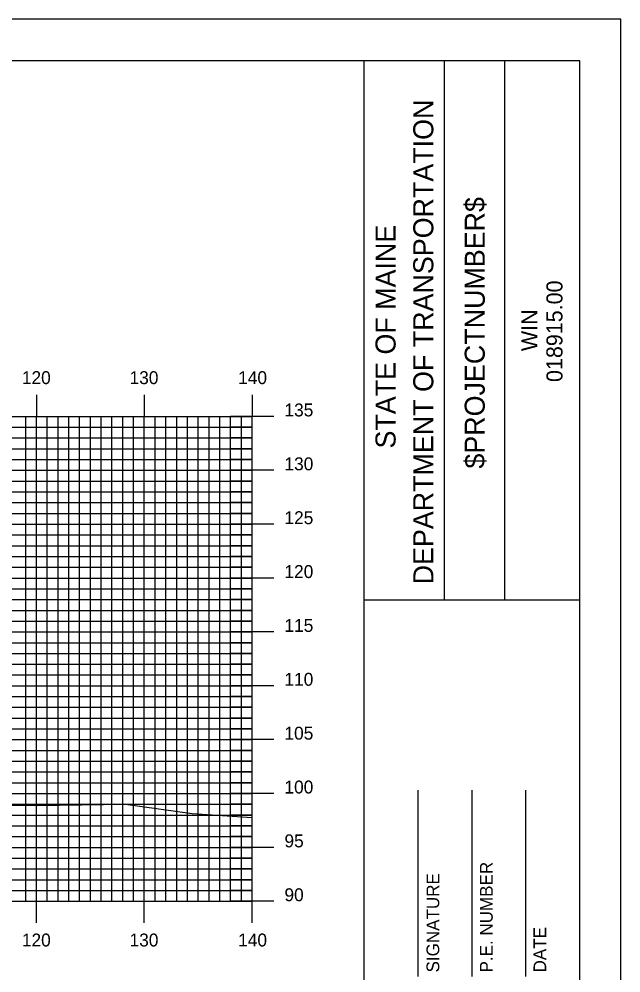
# Model space of a CAD drawing. Extents: x 1785402 to 1785745, y 442591 to 442811.
# Drawn here: x 1785685.9 to 1785741.8, y 442722 to 442810.5 of the extents above; entities that cross this region are included whole.
import ezdxf

# ---------------------------------------------------------------- set-up
doc = ezdxf.new("R2010")
doc.units = 0
for name, color, linetype in [('BORDER', 7, 'Continuous'), ('H_V ANNOTATION', 7, 'Continuous'), ('MAJOR', 7, 'Continuous'), ('MINOR', 7, 'Continuous'), ('PLOT BOUNDARY', 7, 'Continuous'), ('S_Roadway_Centerline', 7, 'Continuous')]:
    doc.layers.add(name, color=color, linetype=linetype)

msp = doc.modelspace()

# ---------------------------------------------------------------- linework, layer by layer
at = {"layer": 'BORDER'}
for p, q in [((1785717.939, 442596.665), (1785717.939, 442806.665)), ((1785725.396, 442756.659), (1785725.396, 442806.659)), ((1785730.986, 442756.659), (1785730.986, 442806.659)), ((1785717.941, 442756.653), (1785737.939, 442756.653)), ((1785717.941, 442756.653), (1785737.939, 442756.653)), ((1785722.939, 442721.671), (1785722.939, 442738.966)), ((1785722.939, 442721.671), (1785722.939, 442738.966)), ((1785727.939, 442721.671), (1785727.939, 442738.966)), ((1785727.939, 442721.671), (1785727.939, 442738.966)), ((1785732.939, 442721.671), (1785732.939, 442738.966)), ((1785732.939, 442721.671), (1785732.939, 442738.966))]:
    msp.add_line(p, q, dxfattribs=at)
msp.add_lwpolyline([(1785417.939, 442596.665), (1785737.939, 442596.665), (1785737.939, 442806.665), (1785417.939, 442806.665)], close=True, dxfattribs=at)
at = {"layer": 'MAJOR'}
for p, q in [((1785687.539, 442775.669), (1785687.539, 442773.665)), ((1785697.539, 442775.669), (1785697.539, 442773.665)), ((1785707.539, 442775.669), (1785707.539, 442773.665)), ((1785427.539, 442773.665), (1785707.539, 442773.665)), ((1785427.539, 442773.665), (1785707.539, 442773.665)), ((1785687.539, 442728.665), (1785687.539, 442773.665)), ((1785697.539, 442728.665), (1785697.539, 442773.665)), ((1785709.543, 442773.665), (1785705.535, 442773.665)), ((1785707.539, 442728.665), (1785707.539, 442773.665)), ((1785707.539, 442728.665), (1785707.539, 442773.665)), ((1785427.539, 442768.665), (1785707.539, 442768.665)), ((1785709.543, 442768.665), (1785705.535, 442768.665)), ((1785427.539, 442763.665), (1785707.539, 442763.665)), ((1785709.543, 442763.665), (1785705.535, 442763.665)), ((1785427.539, 442758.665), (1785707.539, 442758.665)), ((1785709.543, 442758.665), (1785705.535, 442758.665)), ((1785427.539, 442753.665), (1785707.539, 442753.665)), ((1785709.543, 442753.665), (1785705.535, 442753.665)), ((1785427.539, 442748.665), (1785707.539, 442748.665)), ((1785709.543, 442748.665), (1785705.535, 442748.665)), ((1785427.539, 442743.665), (1785707.539, 442743.665)), ((1785709.543, 442743.665), (1785705.535, 442743.665)), ((1785427.539, 442738.665), (1785707.539, 442738.665)), ((1785709.543, 442738.665), (1785705.535, 442738.665)), ((1785427.539, 442733.665), (1785707.539, 442733.665)), ((1785709.543, 442733.665), (1785705.535, 442733.665)), ((1785427.539, 442728.665), (1785707.539, 442728.665)), ((1785427.539, 442728.665), (1785707.539, 442728.665)), ((1785687.539, 442726.661), (1785687.539, 442728.665)), ((1785697.539, 442726.661), (1785697.539, 442728.665)), ((1785709.543, 442728.665), (1785705.535, 442728.665)), ((1785707.539, 442726.661), (1785707.539, 442728.665))]:
    msp.add_line(p, q, dxfattribs=at)
at = {"layer": 'MINOR'}
for p, q in [((1785686.539, 442728.665), (1785686.539, 442773.665)), ((1785688.539, 442728.665), (1785688.539, 442773.665)), ((1785689.539, 442728.665), (1785689.539, 442773.665)), ((1785690.539, 442728.665), (1785690.539, 442773.665)), ((1785691.539, 442728.665), (1785691.539, 442773.665)), ((1785692.539, 442728.665), (1785692.539, 442773.665)), ((1785693.539, 442728.665), (1785693.539, 442773.665)), ((1785694.539, 442728.665), (1785694.539, 442773.665)), ((1785695.539, 442728.665), (1785695.539, 442773.665)), ((1785696.539, 442728.665), (1785696.539, 442773.665)), ((1785698.539, 442728.665), (1785698.539, 442773.665)), ((1785699.539, 442728.665), (1785699.539, 442773.665)), ((1785700.539, 442728.665), (1785700.539, 442773.665)), ((1785701.539, 442728.665), (1785701.539, 442773.665)), ((1785702.539, 442728.665), (1785702.539, 442773.665)), ((1785703.539, 442728.665), (1785703.539, 442773.665)), ((1785704.539, 442728.665), (1785704.539, 442773.665)), ((1785705.539, 442728.665), (1785705.539, 442773.665)), ((1785706.539, 442728.665), (1785706.539, 442773.665)), ((1785427.539, 442772.665), (1785707.539, 442772.665)), ((1785707.539, 442772.665), (1785705.535, 442772.665)), ((1785427.539, 442771.665), (1785707.539, 442771.665)), ((1785707.539, 442771.665), (1785705.535, 442771.665)), ((1785427.539, 442770.665), (1785707.539, 442770.665)), ((1785707.539, 442770.665), (1785705.535, 442770.665)), ((1785427.539, 442769.665), (1785707.539, 442769.665)), ((1785707.539, 442769.665), (1785705.535, 442769.665)), ((1785427.539, 442767.665), (1785707.539, 442767.665)), ((1785707.539, 442767.665), (1785705.535, 442767.665)), ((1785427.539, 442766.665), (1785707.539, 442766.665)), ((1785707.539, 442766.665), (1785705.535, 442766.665)), ((1785427.539, 442765.665), (1785707.539, 442765.665)), ((1785707.539, 442765.665), (1785705.535, 442765.665)), ((1785427.539, 442764.665), (1785707.539, 442764.665)), ((1785707.539, 442764.665), (1785705.535, 442764.665)), ((1785427.539, 442762.665), (1785707.539, 442762.665)), ((1785707.539, 442762.665), (1785705.535, 442762.665)), ((1785427.539, 442761.665), (1785707.539, 442761.665)), ((1785707.539, 442761.665), (1785705.535, 442761.665)), ((1785427.539, 442760.665), (1785707.539, 442760.665)), ((1785707.539, 442760.665), (1785705.535, 442760.665)), ((1785427.539, 442759.665), (1785707.539, 442759.665)), ((1785707.539, 442759.665), (1785705.535, 442759.665)), ((1785427.539, 442757.665), (1785707.539, 442757.665)), ((1785707.539, 442757.665), (1785705.535, 442757.665)), ((1785427.539, 442756.665), (1785707.539, 442756.665)), ((1785707.539, 442756.665), (1785705.535, 442756.665)), ((1785427.539, 442755.665), (1785707.539, 442755.665)), ((1785707.539, 442755.665), (1785705.535, 442755.665)), ((1785427.539, 442754.665), (1785707.539, 442754.665)), ((1785707.539, 442754.665), (1785705.535, 442754.665)), ((1785427.539, 442752.665), (1785707.539, 442752.665)), ((1785707.539, 442752.665), (1785705.535, 442752.665)), ((1785427.539, 442751.665), (1785707.539, 442751.665)), ((1785707.539, 442751.665), (1785705.535, 442751.665)), ((1785427.539, 442750.665), (1785707.539, 442750.665)), ((1785707.539, 442750.665), (1785705.535, 442750.665)), ((1785427.539, 442749.665), (1785707.539, 442749.665)), ((1785707.539, 442749.665), (1785705.535, 442749.665)), ((1785427.539, 442747.665), (1785707.539, 442747.665)), ((1785707.539, 442747.665), (1785705.535, 442747.665)), ((1785427.539, 442746.665), (1785707.539, 442746.665)), ((1785707.539, 442746.665), (1785705.535, 442746.665)), ((1785427.539, 442745.665), (1785707.539, 442745.665)), ((1785707.539, 442745.665), (1785705.535, 442745.665)), ((1785427.539, 442744.665), (1785707.539, 442744.665)), ((1785707.539, 442744.665), (1785705.535, 442744.665)), ((1785427.539, 442742.665), (1785707.539, 442742.665)), ((1785707.539, 442742.665), (1785705.535, 442742.665)), ((1785427.539, 442741.665), (1785707.539, 442741.665)), ((1785707.539, 442741.665), (1785705.535, 442741.665)), ((1785427.539, 442740.665), (1785707.539, 442740.665)), ((1785707.539, 442740.665), (1785705.535, 442740.665)), ((1785427.539, 442739.665), (1785707.539, 442739.665)), ((1785707.539, 442739.665), (1785705.535, 442739.665)), ((1785427.539, 442737.665), (1785707.539, 442737.665)), ((1785707.539, 442737.665), (1785705.535, 442737.665)), ((1785427.539, 442736.665), (1785707.539, 442736.665)), ((1785707.539, 442736.665), (1785705.535, 442736.665)), ((1785427.539, 442735.665), (1785707.539, 442735.665)), ((1785707.539, 442735.665), (1785705.535, 442735.665)), ((1785427.539, 442734.665), (1785707.539, 442734.665)), ((1785707.539, 442734.665), (1785705.535, 442734.665)), ((1785427.539, 442732.665), (1785707.539, 442732.665)), ((1785707.539, 442732.665), (1785705.535, 442732.665)), ((1785427.539, 442731.665), (1785707.539, 442731.665)), ((1785707.539, 442731.665), (1785705.535, 442731.665)), ((1785427.539, 442730.665), (1785707.539, 442730.665)), ((1785707.539, 442730.665), (1785705.535, 442730.665)), ((1785427.539, 442729.665), (1785707.539, 442729.665)), ((1785707.539, 442729.665), (1785705.535, 442729.665))]:
    msp.add_line(p, q, dxfattribs=at)
at = {"layer": 'PLOT BOUNDARY'}
msp.add_lwpolyline([(1785401.752, 442590.547), (1785741.752, 442590.547), (1785741.752, 442810.547), (1785401.752, 442810.547)], close=True, dxfattribs=at)
at = {"layer": 'S_Roadway_Centerline'}
msp.add_lwpolyline([(1785618.773, 442743.37), (1785637.991, 442741.7), (1785639.632, 442741.606), (1785650.02, 442741.204), (1785660.414, 442739.773), (1785661.375, 442739.775), (1785662.615, 442739.643), (1785681.418, 442737.597), (1785687.643, 442737.554), (1785695.805, 442737.689), (1785701.989, 442736.798), (1785707.539, 442736.423)], dxfattribs=at)

# ---------------------------------------------------------------- texts
at = {"layer": 'BORDER'}
for s, height, p in [('DEPARTMENT OF TRANSPORTATION', 1.86351, (1785724.352, 442758.077)), ('$PROJECTNUMBER$', 1.86351, (1785729.123, 442768.823)), ('STATE OF MAINE', 1.86351, (1785720.849, 442770.689)), ('018915.00', 1.4905, (1785736.33, 442776.861)), ('WIN', 1.4905, (1785734.012, 442779.725)), ('P.E. NUMBER', 1.1811, (1785729.86, 442722.055)), ('P.E. NUMBER', 1.1811, (1785729.86, 442722.055)), ('SIGNATURE', 1.1811, (1785724.9, 442722.055)), ('SIGNATURE', 1.1811, (1785724.9, 442722.055)), ('DATE', 1.1811, (1785734.821, 442722.055)), ('DATE', 1.1811, (1785734.821, 442722.055))]:
    msp.add_text(s, height=height, rotation=90, dxfattribs=at).set_placement(p)
at = {"layer": 'H_V ANNOTATION'}
for s, p in [('120', (1785686.179, 442776.665)), ('130', (1785696.169, 442776.665)), ('140', (1785706.244, 442776.665)), ('135', (1785710.539, 442773.665)), ('130', (1785710.539, 442768.665)), ('125', (1785710.539, 442763.665)), ('120', (1785710.539, 442758.665)), ('115', (1785710.539, 442753.665)), ('110', (1785710.539, 442748.665)), ('105', (1785710.539, 442743.665)), ('100', (1785710.539, 442738.665)), ('95', (1785710.539, 442733.665)), ('90', (1785710.539, 442728.665)), ('120', (1785686.179, 442724.465)), ('130', (1785696.169, 442724.465)), ('140', (1785706.244, 442724.465))]:
    msp.add_text(s, height=1.2, dxfattribs=at).set_placement(p)

doc.saveas('drawing.dxf')
